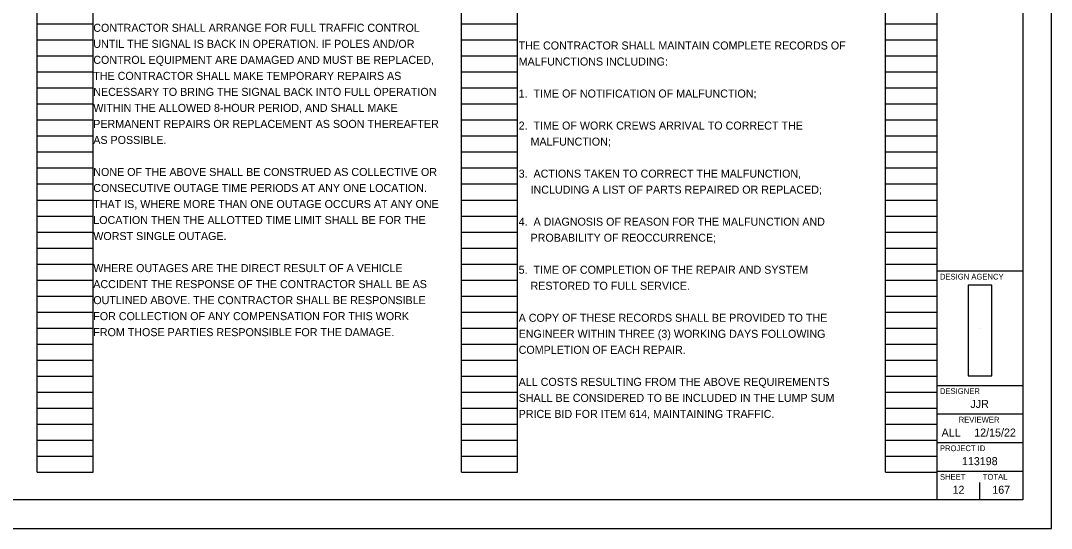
# Model space of a CAD drawing. Extents: x -6.8 to 34, y 0 to 22.
# Drawn here: x 15.97 to 34, y 0 to 8.88 of the extents above; entities that cross this region are included whole.
import ezdxf

# ---------------------------------------------------------------- set-up
doc = ezdxf.new("R2010")
doc.units = 0
for name, color, linetype in [('SH_Border', 7, 'Continuous'), ('SH_Cut_Line', 7, 'Continuous'), ('SH_Data', 7, 'Continuous'), ('SH_Text', 7, 'Continuous')]:
    doc.layers.add(name, color=color, linetype=linetype)

msp = doc.modelspace()

# ---------------------------------------------------------------- linework, layer by layer
at = {"layer": 'SH_Border'}
for p, q in [((32, 0.5), (32, 21.5)), ((32, 4.5), (33.5, 4.5)), ((32, 2.5), (33.5, 2.5)), ((32, 2), (33.5, 2)), ((32, 1.5), (33.5, 1.5)), ((32, 1), (33.5, 1))]:
    msp.add_line(p, q, dxfattribs=at)
msp.add_lwpolyline([(1.5, 21.5), (33.5, 21.5), (33.5, 0.5), (1.5, 0.5)], close=True, dxfattribs=at)
at = {"layer": 'SH_Cut_Line'}
msp.add_lwpolyline([(0, 0), (34, 0), (34, 22), (0, 22)], close=True, dxfattribs=at)
at = {"layer": 'SH_Data'}
for p, q in [((16.26, 0.98), (16.26, 21.14)), ((17.24, 0.98), (17.24, 21.14)), ((23.68, 0.98), (23.68, 21.14)), ((24.66, 0.98), (24.66, 21.14)), ((31.1, 0.98), (31.1, 21.14)), ((32, 0.98), (32, 21.14)), ((16.26, 8.82), (17.24, 8.82)), ((23.68, 8.82), (24.66, 8.82)), ((31.1, 8.82), (32, 8.82)), ((16.26, 8.54), (17.24, 8.54)), ((23.68, 8.54), (24.66, 8.54)), ((31.1, 8.54), (32, 8.54)), ((16.26, 8.26), (17.24, 8.26)), ((23.68, 8.26), (24.66, 8.26)), ((31.1, 8.26), (32, 8.26)), ((16.26, 7.98), (17.24, 7.98)), ((23.68, 7.98), (24.66, 7.98)), ((31.1, 7.98), (32, 7.98)), ((16.26, 7.7), (17.24, 7.7)), ((23.68, 7.7), (24.66, 7.7)), ((31.1, 7.7), (32, 7.7)), ((16.26, 7.42), (17.24, 7.42)), ((23.68, 7.42), (24.66, 7.42)), ((31.1, 7.42), (32, 7.42)), ((16.26, 7.14), (17.24, 7.14)), ((23.68, 7.14), (24.66, 7.14)), ((31.1, 7.14), (32, 7.14)), ((16.26, 6.86), (17.24, 6.86)), ((23.68, 6.86), (24.66, 6.86)), ((31.1, 6.86), (32, 6.86)), ((16.26, 6.58), (17.24, 6.58)), ((23.68, 6.58), (24.66, 6.58)), ((31.1, 6.58), (32, 6.58)), ((16.26, 6.3), (17.24, 6.3)), ((23.68, 6.3), (24.66, 6.3)), ((31.1, 6.3), (32, 6.3)), ((16.26, 6.02), (17.24, 6.02)), ((23.68, 6.02), (24.66, 6.02)), ((31.1, 6.02), (32, 6.02)), ((16.26, 5.74), (17.24, 5.74)), ((23.68, 5.74), (24.66, 5.74)), ((31.1, 5.74), (32, 5.74)), ((16.26, 5.46), (17.24, 5.46)), ((23.68, 5.46), (24.66, 5.46)), ((31.1, 5.46), (32, 5.46)), ((16.26, 5.18), (17.24, 5.18)), ((23.68, 5.18), (24.66, 5.18)), ((31.1, 5.18), (32, 5.18)), ((16.26, 4.9), (17.24, 4.9)), ((23.68, 4.9), (24.66, 4.9)), ((31.1, 4.9), (32, 4.9)), ((16.26, 4.62), (17.24, 4.62)), ((23.68, 4.62), (24.66, 4.62)), ((31.1, 4.62), (32, 4.62)), ((16.26, 4.34), (17.24, 4.34)), ((23.68, 4.34), (24.66, 4.34)), ((31.1, 4.34), (32, 4.34)), ((16.26, 4.06), (17.24, 4.06)), ((23.68, 4.06), (24.66, 4.06)), ((31.1, 4.06), (32, 4.06)), ((16.26, 3.78), (17.24, 3.78)), ((23.68, 3.78), (24.66, 3.78)), ((31.1, 3.78), (32, 3.78)), ((16.26, 3.5), (17.24, 3.5)), ((23.68, 3.5), (24.66, 3.5)), ((31.1, 3.5), (32, 3.5)), ((32.75, 3.5), (32.75, 3.5)), ((16.26, 3.22), (17.24, 3.22)), ((23.68, 3.22), (24.66, 3.22)), ((31.1, 3.22), (32, 3.22)), ((16.26, 2.94), (17.24, 2.94)), ((23.68, 2.94), (24.66, 2.94)), ((31.1, 2.94), (32, 2.94)), ((16.26, 2.66), (17.24, 2.66)), ((23.68, 2.66), (24.66, 2.66)), ((31.1, 2.66), (32, 2.66)), ((16.26, 2.38), (17.24, 2.38)), ((23.68, 2.38), (24.66, 2.38)), ((31.1, 2.38), (32, 2.38)), ((16.26, 2.1), (17.24, 2.1)), ((23.68, 2.1), (24.66, 2.1)), ((31.1, 2.1), (32, 2.1)), ((16.26, 1.82), (17.24, 1.82)), ((23.68, 1.82), (24.66, 1.82)), ((31.1, 1.82), (32, 1.82)), ((16.26, 1.54), (17.24, 1.54)), ((23.68, 1.54), (24.66, 1.54)), ((31.1, 1.54), (32, 1.54)), ((16.26, 1.26), (17.24, 1.26)), ((23.68, 1.26), (24.66, 1.26)), ((31.1, 1.26), (32, 1.26)), ((16.26, 0.98), (17.24, 0.98)), ((23.68, 0.98), (24.66, 0.98)), ((31.1, 0.98), (32, 0.98)), ((32.75, 0.5), (32.75, 0.8)), ((32.375, 0.675), (32.375, 0.675))]:
    msp.add_line(p, q, dxfattribs=at)
at = {"layer": 'SH_Text'}
msp.add_lwpolyline([(32.956, 2.664), (32.956, 4.254), (32.544, 4.254), (32.544, 2.664)], close=True, dxfattribs=at)

# ---------------------------------------------------------------- texts
at = {"layer": 'SH_Data'}
for s, height, p in [('DESIGN AGENCY', 0.1, (32.05, 4.35)), ('DESIGNER', 0.1, (32.05, 2.35)), ('JJR', 0.14, (32.583, 2.105)), ('REVIEWER', 0.1, (32.378, 1.85)), ('ALL', 0.14, (32.079, 1.605)), ('12/15/22', 0.14, (32.65, 1.605)), ('PROJECT ID', 0.1, (32.05, 1.35)), ('113198', 0.14, (32.435, 1.105)), ('SHEET', 0.1, (32.05, 0.85)), ('TOTAL', 0.1, (32.8, 0.85)), ('12', 0.14, (32.271, 0.605)), ('167', 0.14, (32.966, 0.605))]:
    msp.add_text(s, height=height, dxfattribs=at).set_placement(p)
at = {"layer": 'SH_Text'}
for s, p in [('CONTRACTOR SHALL ARRANGE FOR FULL TRAFFIC CONTROL', (17.24, 8.68)), ('UNTIL THE SIGNAL IS BACK IN OPERATION. IF POLES AND/OR', (17.24, 8.4)), ('THE CONTRACTOR SHALL MAINTAIN COMPLETE RECORDS OF', (24.681, 8.371)), ('CONTROL EQUIPMENT ARE DAMAGED AND MUST BE REPLACED,', (17.24, 8.12)), ('MALFUNCTIONS INCLUDING:', (24.681, 8.091)), ('THE CONTRACTOR SHALL MAKE TEMPORARY REPAIRS AS', (17.24, 7.84)), ('NECESSARY TO BRING THE SIGNAL BACK INTO FULL OPERATION', (17.24, 7.56)), ('1.  TIME OF NOTIFICATION OF MALFUNCTION;', (24.681, 7.531)), ('WITHIN THE ALLOWED 8-HOUR PERIOD, AND SHALL MAKE', (17.24, 7.28)), ('PERMANENT REPAIRS OR REPLACEMENT AS SOON THEREAFTER', (17.24, 7)), ('2.  TIME OF WORK CREWS ARRIVAL TO CORRECT THE', (24.681, 6.971)), ('AS POSSIBLE.', (17.24, 6.72)), ('    MALFUNCTION;', (24.681, 6.691)), ('NONE OF THE ABOVE SHALL BE CONSTRUED AS COLLECTIVE OR', (17.24, 6.16)), ('3.  ACTIONS TAKEN TO CORRECT THE MALFUNCTION,', (24.681, 6.131)), ('CONSECUTIVE OUTAGE TIME PERIODS AT ANY ONE LOCATION.', (17.24, 5.88)), ('    INCLUDING A LIST OF PARTS REPAIRED OR REPLACED;', (24.681, 5.851)), ('THAT IS, WHERE MORE THAN ONE OUTAGE OCCURS AT ANY ONE', (17.24, 5.6)), ('LOCATION THEN THE ALLOTTED TIME LIMIT SHALL BE FOR THE', (17.24, 5.32)), ('4.  A DIAGNOSIS OF REASON FOR THE MALFUNCTION AND', (24.681, 5.291)), ('WORST SINGLE OUTAGE.', (17.24, 5.04)), ('    PROBABILITY OF REOCCURRENCE;', (24.681, 5.011)), ('WHERE OUTAGES ARE THE DIRECT RESULT OF A VEHICLE', (17.24, 4.48)), ('5.  TIME OF COMPLETION OF THE REPAIR AND SYSTEM', (24.681, 4.451)), ('ACCIDENT THE RESPONSE OF THE CONTRACTOR SHALL BE AS', (17.24, 4.2)), ('    RESTORED TO FULL SERVICE.', (24.681, 4.171)), ('OUTLINED ABOVE. THE CONTRACTOR SHALL BE RESPONSIBLE', (17.24, 3.92)), ('FOR COLLECTION OF ANY COMPENSATION FOR THIS WORK', (17.24, 3.64)), ('A COPY OF THESE RECORDS SHALL BE PROVIDED TO THE', (24.681, 3.611)), ('FROM THOSE PARTIES RESPONSIBLE FOR THE DAMAGE.', (17.24, 3.36)), ('ENGINEER WITHIN THREE (3) WORKING DAYS FOLLOWING', (24.681, 3.331)), ('COMPLETION OF EACH REPAIR.', (24.681, 3.051)), ('ALL COSTS RESULTING FROM THE ABOVE REQUIREMENTS', (24.681, 2.491)), ('SHALL BE CONSIDERED TO BE INCLUDED IN THE LUMP SUM', (24.681, 2.211)), ('PRICE BID FOR ITEM 614, MAINTAINING TRAFFIC.', (24.681, 1.931))]:
    msp.add_text(s, height=0.14, dxfattribs=at).set_placement(p)

doc.saveas('drawing.dxf')
